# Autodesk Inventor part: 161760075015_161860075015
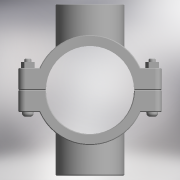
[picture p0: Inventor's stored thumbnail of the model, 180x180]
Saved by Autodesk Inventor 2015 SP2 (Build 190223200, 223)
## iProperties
Created: 2017-05
Part Number: 161760075015_161860075015
Material: Generic
Description: PLASSON DOUBLE SADDLE 75-1.1/2"
Document SubType Name: Modeling
Designer: KIM
Density: 1 g/cm^3
Appearance: Default
Author: KIM
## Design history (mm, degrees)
derived "16176.ipt"
feature "Solid1::16176.ipt"
feature "Solid2::16176.ipt"
tag "TaggingFeature1"
body "Solid1"
body "Solid2"
other parameters: "d0" = 93.75, "d1" = 122, "d2" = 37.5, "d3" = 75, "d4" = 98, "d5" = 0, "d6" = 6.1, "d7" = 122, "d8" = 0.1, "d10" = 0, "d11" = 0.75, "d20" = 0.75, "d23" = 0.75, "d37" = 8, "d38" = 45.5, "d39" = 0, "d40" = 3, "d41" = 5, "d42" = 0, "d43" = 6, "d44" = 3, "d45" = 0, "d46" = 0.75, "d52" = 44.845, "d53" = 25, "d54" = 0, "d57" = 0, "d58" = 81, "d60" = 0, "d63" = 8, "d66" = 82, "d67" = 146, "d68" = 58.2985, "d69" = 44.845, "d70" = 25, "d71" = 0, "d74" = 0, "d75" = 0.75, "d_" = 75, "G_" = 44.845, "A_" = 73, "L_" = 122, "L_1" = 98, "l_2" = 25
